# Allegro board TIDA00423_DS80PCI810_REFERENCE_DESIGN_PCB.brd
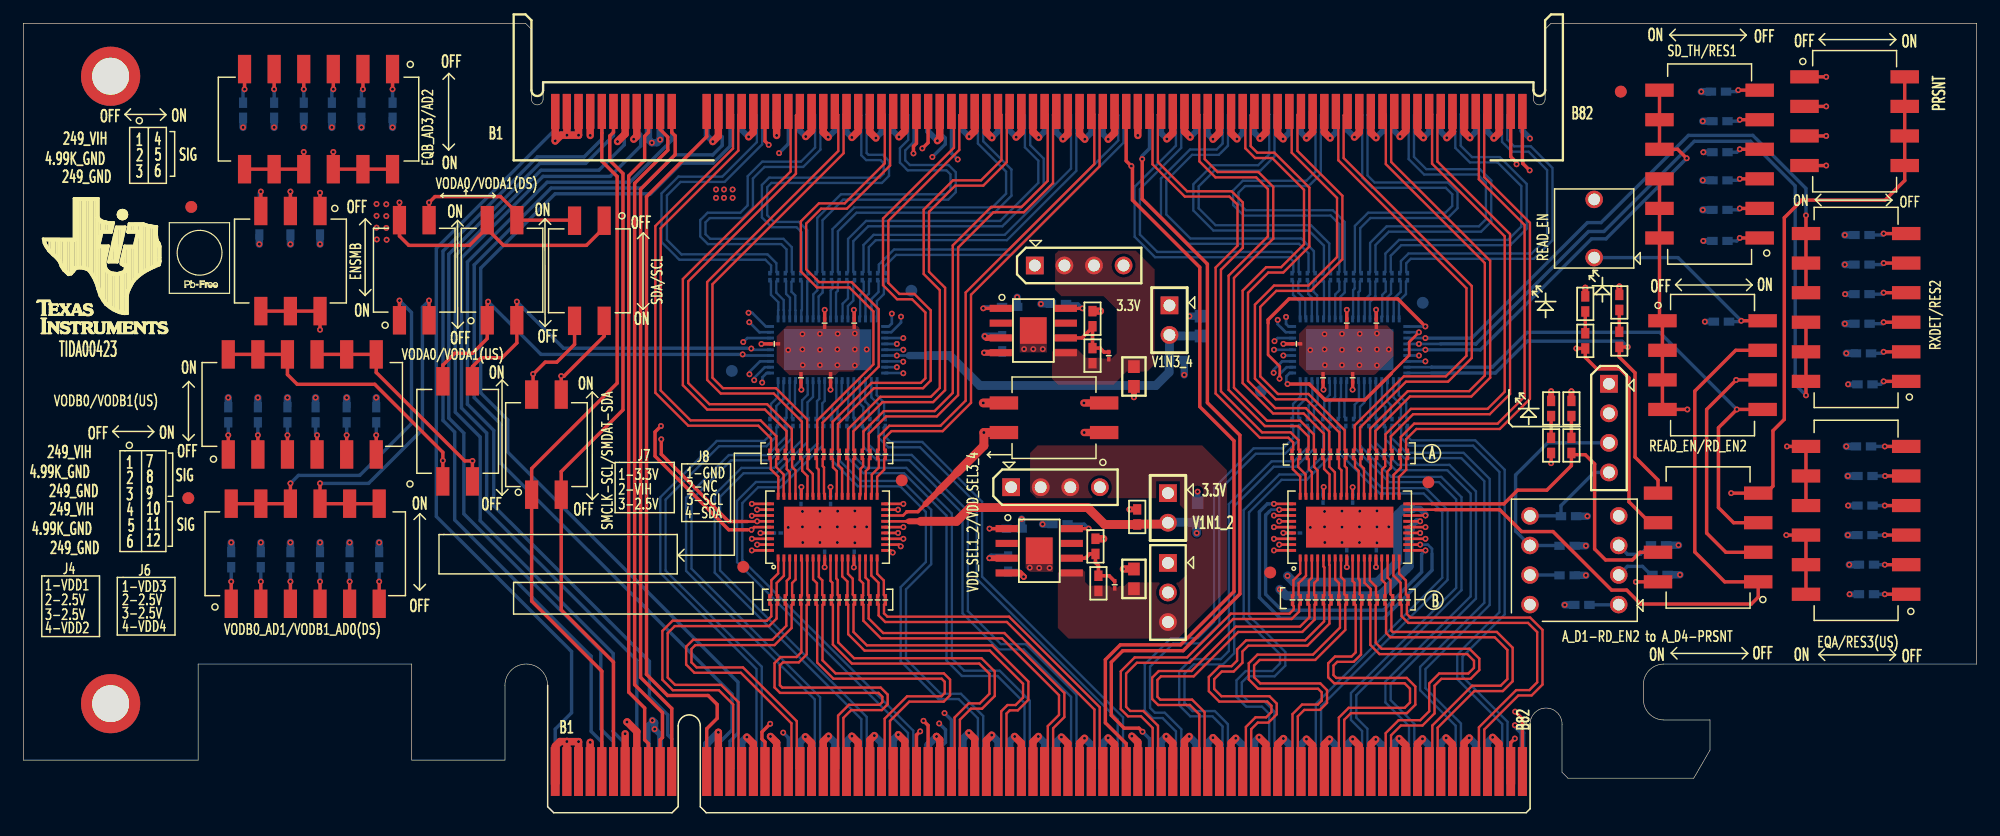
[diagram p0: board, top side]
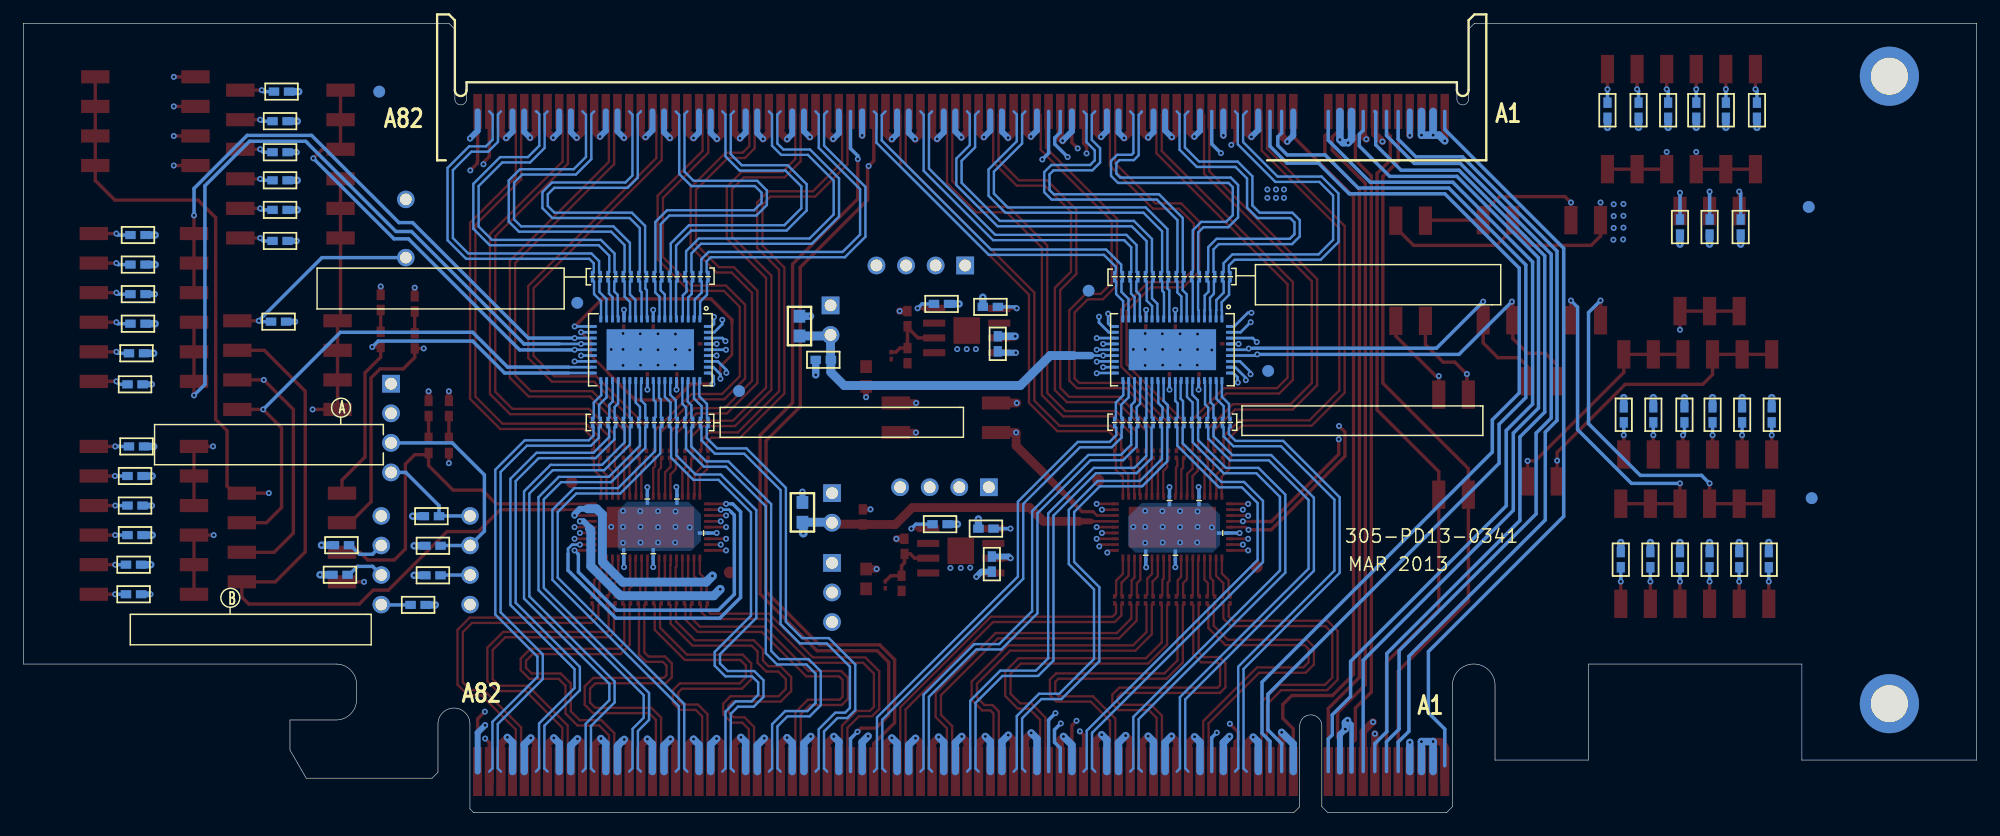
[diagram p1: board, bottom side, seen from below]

Outline 167.64 x 67.82 mm; copper layers: TOP, GND1, POWER1, POWER2, GND2, BOTTOM. Coordinates in mm from the lower left corner of the outline.
Outline path: 0,67.82 0,4.52 15,4.52 15,12.77 33.33,12.77 33.33,4.52 41.34,4.52 41.34,10.95 arc(43.16,12.77) 44.99,10.95 44.99,0.52 45.51,0 55.68,0 56.2,0.52 56.2,7.47 arc(57.15,8.42) 58.1,7.47 58.1,0.51 58.61,0 128.98,0 129.31,0.34 129.31,7.62 arc(130.68,8.99) 132.05,7.62 132.05,3.47 132.56,2.97 143.36,2.97 144.75,5.39 144.75,7.97 140.79,7.97 arc(139.55,8.48) 139.04,9.72 139.04,11.02 arc(139.55,12.26) 140.79,12.77 167.64,12.77 167.64,67.82 131.11,67.82 130.6,67.31 130.6,61.31 arc(130.1,60.81) 129.6,61.31 129.6,62.74 44.61,62.74 44.61,61.31 arc(44.11,60.81) 43.61,61.31 43.61,67.31 43.1,67.82 0,67.82

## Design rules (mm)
net group A_D1: nets A_D1 N144905650
net group A_D2: nets A_D2 N144912360
net group A_D3: nets A_D3 N144909880
net group A_D4: nets A_D4 N144914850
net group PERN0: nets N708449616 PERN0
net group PERN0_C: nets N144793501 PERN0_C
net group PERN1: nets N708449621 PERN1
net group PERN1_C: nets N144768421 PERN1_C
net group PERN2: nets N708449625 PERN2
net group PERN2_C: nets N144768181 PERN2_C
net group PERN3: nets N708449629 PERN3
net group PERN3_C: nets N144794701 PERN3_C
net group PERN4: nets N708449635 PERN4
net group PERN4_C: nets N144796981 PERN4_C
net group PERN5: nets N708449639 PERN5
net group PERN5_C: nets N144780601 PERN5_C
net group PERN6: nets N708449643 PERN6
net group PERN6_C: nets N144778981 PERN6_C
net group PERN7: nets N708449647 PERN7
net group PERN7_C: nets N144766261 PERN7_C
net group PERN8: nets N708449652 PERN8
net group PERN8_C: nets N144777781 PERN8_C
net group PERN9: nets N708449656 PERN9
net group PERN9_C: nets N144778201 PERN9_C
net group PERN10: nets N708449660 PERN10
net group PERN10_C: nets N144778741 PERN10_C
net group PERN11: nets N708449664 PERN11
net group PERN11_C: nets N144777421 PERN11_C
net group PERN12: nets N708449668 PERN12
net group PERN12_C: nets N144796741 PERN12_C
net group PERN13: nets N708449672 PERN13
net group PERN13_C: nets N144769921 PERN13_C
net group PERN14: nets N708449676 PERN14
net group PERN14_C: nets N144775501 PERN14_C
net group PERN15: nets N708449680 PERN15
net group PERN15_C: nets N144767221 PERN15_C
net group PERP0: nets N708449615 PERP0
net group PERP0_C: nets N144792241 PERP0_C
net group PERP1: nets N708449620 PERP1
net group PERP1_C: nets N144791101 PERP1_C
net group PERP2: nets N708449624 PERP2
net group PERP2_C: nets N144794401 PERP2_C
net group PERP3: nets N708449628 PERP3
net group PERP3_C: nets N144773581 PERP3_C
net group PERP4: nets N708449634 PERP4
net group PERP4_C: nets N144792841 PERP4_C
net group PERP5: nets N708449638 PERP5
net group PERP5_C: nets N144771181 PERP5_C
net group PERP6: nets N708449642 PERP6
net group PERP6_C: nets N144780361 PERP6_C
net group PERP7: nets N708449646 PERP7
net group PERP7_C: nets N144773341 PERP7_C
net group PERP8: nets N708449651 PERP8
net group PERP8_C: nets N144769021 PERP8_C
net group PERP9: nets N708449655 PERP9
net group PERP9_C: nets N144788821 PERP9_C
net group PERP10: nets N708449659 PERP10
net group PERP10_C: nets N144768781 PERP10_C
net group PERP11: nets N708449663 PERP11
net group PERP11_C: nets N144772741 PERP11_C
net group PERP12: nets N708449667 PERP12
net group PERP12_C: nets N144777181 PERP12_C
net group PERP13: nets N708449671 PERP13
net group PERP13_C: nets N144766561 PERP13_C
net group PERP14: nets N708449675 PERP14
net group PERP14_C: nets N144795421 PERP14_C
net group PERP15: nets N708449679 PERP15
net group PERP15_C: nets N144788221 PERP15_C
net group PETN0: nets N708449696 PETN0
net group PETN0_C: nets N144795060 PETN0_C
net group PETN1: nets N7084496101 PETN1
net group PETN1_C: nets N144774480 PETN1_C
net group PETN2: nets N7084496105 PETN2
net group PETN2_C: nets N144776640 PETN2_C
net group PETN3: nets N7084496109 PETN3
net group PETN3_C: nets N144771900 PETN3_C
net group PETN4: nets N7084496115 PETN4
net group PETN4_C: nets N144790620 PETN4_C
net group PETN5: nets N7084496119 PETN5
net group PETN5_C: nets N144770280 PETN5_C
net group PETN6: nets N7084496123 PETN6
net group PETN6_C: nets N144771420 PETN6_C
net group PETN7: nets N7084496127 PETN7
net group PETN7_C: nets N144775140 PETN7_C
net group PETN8: nets N7084496132 PETN8
net group PETN8_C: nets N144795720 PETN8_C
net group PETN9: nets N7084496136 PETN9
net group PETN9_C: nets N144776160 PETN9_C
net group PETN10: nets N7084496140 PETN10
net group PETN10_C: nets N144770880 PETN10_C
net group PETN11: nets N7084496144 PETN11
net group PETN11_C: nets N144790260 PETN11_C
net group PETN12: nets N7084496148 PETN12
net group PETN12_C: nets N144772500 PETN12_C
net group PETN13: nets N7084496152 PETN13
net group PETN13_C: nets N144778500 PETN13_C
net group PETN14: nets N7084496156 PETN14
net group PETN14_C: nets N144774000 PETN14_C
net group PETN15: nets N7084496160 PETN15
net group PETN15_C: nets N144791880 PETN15_C
net group PETP0: nets N708449695 PETP0
net group PETP0_C: nets N144769680 PETP0_C
net group PETP1: nets N7084496100 PETP1
net group PETP1_C: nets N144776880 PETP1_C
net group PETP2: nets N7084496104 PETP2
net group PETP2_C: nets N144766980 PETP2_C
net group PETP3: nets N7084496108 PETP3
net group PETP3_C: nets N144779460 PETP3_C
net group PETP4: nets N7084496114 PETP4
net group PETP4_C: nets N144779220 PETP4_C
net group PETP5: nets N7084496118 PETP5
net group PETP5_C: nets N144796260 PETP5_C
net group PETP6: nets N7084496122 PETP6
net group PETP6_C: nets N144789780 PETP6_C
net group PETP7: nets N7084496126 PETP7
net group PETP7_C: nets N144765660 PETP7_C
net group PETP8: nets N7084496131 PETP8
net group PETP8_C: nets N144789240 PETP8_C
net group PETP9: nets N7084496135 PETP9
net group PETP9_C: nets N144794040 PETP9_C
net group PETP10: nets N7084496139 PETP10
net group PETP10_C: nets N144770640 PETP10_C
net group PETP11: nets N7084496143 PETP11
net group PETP11_C: nets N144774240 PETP11_C
net group PETP12: nets N7084496147 PETP12
net group PETP12_C: nets N144793080 PETP12_C
net group PETP13: nets N7084496151 PETP13
net group PETP13_C: nets N144780060 PETP13_C
net group PETP14: nets N7084496155 PETP14
net group PETP14_C: nets N144767760 PETP14_C
net group PETP15: nets N7084496159 PETP15
net group PETP15_C: nets N144772140 PETP15_C
net group VOUT1_2: nets N14347575 VOUT1_2
net group VOUT3_4: nets N14379574 VOUT3_4
net group 3_3V: nets 3_3V N14347847 N14379914
net group SCL: nets N14519010 N14693554 N143603151 N143605671 N144870781 N144872810 N144872813 N144873671 N144875811 N144883340 N144883343 N144883781 N144885701 N144890181 N144891221 SCL SDA VIH

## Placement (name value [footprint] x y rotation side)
C1  0.1uF  [0201]  68.77 22.12 270 bottom
C2  0.1uF  [0201]  64.71 24.03 180 bottom
C3  0.1uF  [0201]  69.28 26.82 90 bottom
C4  0.1uF  [0201]  66.74 26.82 90 bottom
C5  0.1uF  [0201]  71.31 22.12 270 bottom
C6  0.1uF  [0201]  114.08 26.95 90 bottom
C7  0.1uF  [0201]  111.54 26.95 90 bottom
C8  0.1uF  [0201]  109.26 24.03 180 bottom
C9  0.1uF  [0201]  113.58 22.25 270 bottom
C10  0.1uF  [0201]  116.12 22.25 270 bottom
C11  0.1uF  [0201]  71.31 42.06 90 top
C12  0.1uF  [0201]  68.77 42.06 90 top
C13  0.1uF  [0201]  64.45 40.28 180 top
C14  0.1uF  [0201]  69.28 37.36 270 top
C15  0.1uF  [0201]  66.74 37.36 270 top
C16  0.1uF  [0201]  116.12 42.06 90 top
C17  0.1uF  [0201]  113.58 42.06 90 top
C18  0.1uF  [0201]  109.26 40.28 180 top
C19  0.1uF  [0201]  114.08 37.36 270 top
C20  0.1uF  [0201]  111.54 37.36 270 top
C21  10uF  [0603]  100.77 25.8 270 bottom
C22  10uF  [0603]  101.03 41.81 270 bottom
C23  4.7uF  [0402]  84.52 21.36 270 bottom
C24  4.7uF  [0402]  84.01 40.28 270 bottom
C25  0.01uF  [0402]  85.03 24.41 0 bottom
C26  0.01uF  [0402]  84.65 43.46 0 bottom
C27  10uF  [0603]  95.31 20.09 90 top
C28  10uF  [0603]  95.31 37.47 270 top
C29  1nF  [0201]  93.66 19.58 90 top
C30  1nF  [0201]  93.15 39.27 90 top
C31  0.22uF  [0201]  64.07 18.28 90 top
C32  0.22uF  [0201]  64.73 18.28 90 top
C33  0.22uF  [0201]  65.39 18.28 90 top
C34  0.22uF  [0201]  66.05 18.28 90 top
C35  0.22uF  [0201]  66.71 18.28 90 top
C36  0.22uF  [0201]  67.37 18.28 90 top
C37  0.22uF  [0201]  68.03 18.28 90 top
C38  0.22uF  [0201]  68.69 18.28 90 top
C39  0.22uF  [0201]  69.36 18.28 90 top
C40  0.22uF  [0201]  70.02 18.28 90 top
C41  0.22uF  [0201]  70.68 18.28 90 top
C42  0.22uF  [0201]  71.34 18.28 90 top
C43  0.22uF  [0201]  72 18.28 90 top
C44  0.22uF  [0201]  72.66 18.28 90 top
C45  0.22uF  [0201]  73.32 18.28 90 top
C46  0.22uF  [0201]  73.98 18.28 90 top
C47  0.22uF  [0201]  108.93 18.28 90 top
C48  0.22uF  [0201]  109.59 18.28 90 top
C49  0.22uF  [0201]  110.25 18.28 90 top
C50  0.22uF  [0201]  110.91 18.28 90 top
C51  0.22uF  [0201]  111.57 18.28 90 top
C52  0.22uF  [0201]  112.23 18.28 90 top
C53  0.22uF  [0201]  112.89 18.28 90 top
C54  0.22uF  [0201]  113.55 18.28 90 top
C55  0.22uF  [0201]  114.21 18.28 90 top
C56  0.22uF  [0201]  114.87 18.28 90 top
C57  0.22uF  [0201]  115.53 18.28 90 top
C58  0.22uF  [0201]  116.19 18.28 90 top
C59  0.22uF  [0201]  116.85 18.28 90 top
C60  0.22uF  [0201]  117.51 18.28 90 top
C61  0.22uF  [0201]  118.17 18.28 90 top
C62  0.22uF  [0201]  118.83 18.28 90 top
C63  0.22uF  [0201]  64.07 33.52 270 bottom
C64  0.22uF  [0201]  64.73 33.52 270 bottom
C65  0.22uF  [0201]  65.39 33.52 270 bottom
C66  0.22uF  [0201]  66.05 33.52 270 bottom
C67  0.22uF  [0201]  66.71 33.52 270 bottom
C68  0.22uF  [0201]  67.37 33.52 270 bottom
C69  0.22uF  [0201]  68.03 33.52 270 bottom
C70  0.22uF  [0201]  68.69 33.52 270 bottom
C71  0.22uF  [0201]  69.36 33.52 270 bottom
C72  0.22uF  [0201]  70.02 33.52 270 bottom
C73  0.22uF  [0201]  70.68 33.52 270 bottom
C74  0.22uF  [0201]  71.34 33.52 270 bottom
C75  0.22uF  [0201]  72 33.52 270 bottom
C76  0.22uF  [0201]  72.66 33.52 270 bottom
C77  0.22uF  [0201]  73.32 33.52 270 bottom
C78  0.22uF  [0201]  73.98 33.52 270 bottom
C79  0.22uF  [0201]  108.88 33.52 270 bottom
C80  0.22uF  [0201]  109.54 33.52 270 bottom
C81  0.22uF  [0201]  110.2 33.52 270 bottom
C82  0.22uF  [0201]  110.86 33.52 270 bottom
C83  0.22uF  [0201]  111.52 33.52 270 bottom
C84  0.22uF  [0201]  112.18 33.52 270 bottom
C85  0.22uF  [0201]  112.84 33.52 270 bottom
C86  0.22uF  [0201]  113.5 33.52 270 bottom
C87  0.22uF  [0201]  114.16 33.52 270 bottom
C88  0.22uF  [0201]  114.82 33.52 270 bottom
C89  0.22uF  [0201]  115.48 33.52 270 bottom
C90  0.22uF  [0201]  116.14 33.52 270 bottom
C91  0.22uF  [0201]  116.8 33.52 270 bottom
C92  0.22uF  [0201]  117.46 33.52 270 bottom
C93  0.22uF  [0201]  118.12 33.52 270 bottom
C94  0.22uF  [0201]  118.78 33.52 270 bottom
C95  0.22uF  [0201]  64.07 30.79 270 top
C96  0.22uF  [0201]  64.73 30.79 270 top
C97  0.22uF  [0201]  65.39 30.79 270 top
C98  0.22uF  [0201]  66.05 30.79 270 top
C99  0.22uF  [0201]  66.71 30.79 270 top
C100  0.22uF  [0201]  67.37 30.79 270 top
C101  0.22uF  [0201]  68.03 30.79 270 top
C102  0.22uF  [0201]  68.69 30.79 270 top
C103  0.22uF  [0201]  69.36 30.79 270 top
C104  0.22uF  [0201]  70.02 30.79 270 top
C105  0.22uF  [0201]  70.68 30.79 270 top
C106  0.22uF  [0201]  71.34 30.79 270 top
C107  0.22uF  [0201]  72 30.79 270 top
C108  0.22uF  [0201]  72.66 30.79 270 top
C109  0.22uF  [0201]  73.32 30.79 270 top
C110  0.22uF  [0201]  73.98 30.79 270 top
C111  0.22uF  [0201]  108.88 30.79 270 top
C112  0.22uF  [0201]  109.54 30.79 270 top
C113  0.22uF  [0201]  110.2 30.79 270 top
C114  0.22uF  [0201]  110.86 30.79 270 top
C115  0.22uF  [0201]  111.52 30.79 270 top
C116  0.22uF  [0201]  112.18 30.79 270 top
C117  0.22uF  [0201]  112.84 30.79 270 top
C118  0.22uF  [0201]  113.5 30.79 270 top
C119  0.22uF  [0201]  114.16 30.79 270 top
C120  0.22uF  [0201]  114.82 30.79 270 top
C121  0.22uF  [0201]  115.48 30.79 270 top
C122  0.22uF  [0201]  116.14 30.79 270 top
C123  0.22uF  [0201]  116.8 30.79 270 top
C124  0.22uF  [0201]  117.46 30.79 270 top
C125  0.22uF  [0201]  118.12 30.79 270 top
C126  0.22uF  [0201]  118.78 30.79 270 top
C127  0.22uF  [0201]  64.07 46.05 90 bottom
C128  0.22uF  [0201]  64.73 46.05 90 bottom
C129  0.22uF  [0201]  65.39 46.05 90 bottom
C130  0.22uF  [0201]  66.05 46.05 90 bottom
C131  0.22uF  [0201]  66.71 46.05 90 bottom
C132  0.22uF  [0201]  67.37 46.05 90 bottom
C133  0.22uF  [0201]  68.03 46.05 90 bottom
C134  0.22uF  [0201]  68.69 46.05 90 bottom
C135  0.22uF  [0201]  69.36 46.05 90 bottom
C136  0.22uF  [0201]  70.02 46.05 90 bottom
C137  0.22uF  [0201]  70.68 46.05 90 bottom
C138  0.22uF  [0201]  71.34 46.05 90 bottom
C139  0.22uF  [0201]  72 46.05 90 bottom
C140  0.22uF  [0201]  72.66 46.05 90 bottom
C141  0.22uF  [0201]  73.32 46.05 90 bottom
C142  0.22uF  [0201]  73.98 46.05 90 bottom
C143  0.22uF  [0201]  108.88 46.05 90 bottom
C144  0.22uF  [0201]  109.54 46.05 90 bottom
C145  0.22uF  [0201]  110.2 46.05 90 bottom
C146  0.22uF  [0201]  110.86 46.05 90 bottom
C147  0.22uF  [0201]  111.52 46.05 90 bottom
C148  0.22uF  [0201]  112.18 46.05 90 bottom
C149  0.22uF  [0201]  112.84 46.05 90 bottom
C150  0.22uF  [0201]  113.5 46.05 90 bottom
C151  0.22uF  [0201]  114.16 46.05 90 bottom
C152  0.22uF  [0201]  114.82 46.05 90 bottom
C153  0.22uF  [0201]  115.48 46.05 90 bottom
C154  0.22uF  [0201]  116.14 46.05 90 bottom
C155  0.22uF  [0201]  116.8 46.05 90 bottom
C156  0.22uF  [0201]  117.46 46.05 90 bottom
C157  0.22uF  [0201]  118.12 46.05 90 bottom
C158  0.22uF  [0201]  118.78 46.05 90 bottom
C160  1uF  [0402]  95.59 25.41 270 top
C161  1uF  [0402]  98.98 38.91 180 bottom
D1  SML-P12PTT86  [0402]  131.12 34.73 270 top
D2  SML-P12PTT86  [0402]  132.86 34.73 270 top
D3  SML-P12PTT86  [0402]  134.05 43.71 270 top
D4  SML-P12PTT86  [0402]  136.97 43.84 270 top
J1  -  [PCIE_16X_EDGE_FINGER]  53.65 3.54 0 top
J2  -  [NWE82DHRN-T9410]  86.94 68.58 0 top
J3  2 HEADER  [2_HEADER]  98.23 27.45 270 top
J4  4 HEADER  [4_HEADER]  84.77 27.96 0 top
J5  2 HEADER  [2_HEADER]  98.36 43.58 270 top
J6  4 HEADER  [4_HEADER]  86.8 47.01 0 top
J7  3 HEADER  [3_HEADER]  98.23 21.46 270 top
J8  4 HEADER  [4_HEADER]  136.08 36.85 270 top
J9  4808-3004-CP  [DIP8]  133.11 21.69 90 top
NOREF  -  [unnamed]  7.49 63.27 0 top
NOREF#2  -  [#2]  0 4.52 90 top
NOREF#3  -  [unnamed]  14.16 27.02 0 top
NOREF#4  -  [unnamed]  75.39 28.55 0 top
NOREF#5  -  [unnamed]  137.1 61.95 0 top
NOREF#6  -  [#2]  33.33 4.52 0 top
NOREF#7  -  [unnamed]  107.01 20.64 0 top
NOREF#8  -  [#2]  0 68.58 0 top
NOREF#9  -  [#2]  0 4.52 0 top
NOREF#10  -  [unnamed]  61.79 21.12 0 top
NOREF#11  -  [unnamed]  7.49 9.37 0 top
NOREF#12  -  [unnamed]  14.41 52.04 0 top
NOREF#13  -  [#2]  166.88 13.53 90 top
NOREF#14  -  [#2]  15 12.77 0 top
NOREF#15  -  [unnamed]  120.58 28.38 0 top
NOREF#16  -  [unnamed]  137.1 61.95 180 bottom
NOREF#17  -  [unnamed]  60.81 37.95 180 bottom
NOREF#18  -  [unnamed]  120.1 43.81 180 bottom
NOREF#19  -  [unnamed]  76.21 44.84 180 bottom
NOREF#20  -  [unnamed]  106.22 36.23 180 bottom
NOREF#21  -  [unnamed]  14.41 52.04 180 bottom
NOREF#22  -  [unnamed]  14.16 27.02 180 bottom
R1  1.5k  [0402]  92.27 19.71 270 top
R2  1k  [0402]  92.01 22.88 270 top
R3  51k  [0402]  88.96 24.79 0 bottom
R4  1.5k  [0402]  91.76 39.27 270 top
R5  1k  [0402]  91.76 42.44 270 top
R6  51k  [0402]  88.84 43.71 0 bottom
R7  220  [0402]  131.12 31.55 270 top
R8  220  [0402]  132.86 31.55 270 top
R9  220  [0402]  134.05 40.54 270 top
R10  220  [0402]  136.97 40.66 270 top
R11  249  [0402]  31.69 60.35 90 bottom
R12  4.99k  [0402]  29.02 60.35 90 bottom
R13  249  [0402]  26.48 60.35 90 bottom
R14  249  [0402]  24.07 60.35 90 bottom
R15  4.99k  [0402]  21.53 60.35 90 bottom
R16  249  [0402]  18.86 60.35 90 bottom
R17  249  [0402]  25.46 50.31 90 bottom
R18  4.99k  [0402]  22.92 50.31 90 bottom
R19  249  [0402]  20.26 50.31 90 bottom
R20  249  [0402]  17.59 34.19 270 bottom
R21  4.99k  [0402]  20.13 34.19 270 bottom
R22  249  [0402]  22.67 34.19 270 bottom
R23  249  [0402]  25.08 34.19 270 bottom
R24  4.99k  [0402]  27.75 34.19 270 bottom
R25  249  [0402]  30.29 34.19 270 bottom
R26  249  [0402]  17.84 21.74 270 bottom
R27  4.99k  [0402]  20.38 21.74 270 bottom
R28  249  [0402]  22.92 21.74 270 bottom
R29  249  [0402]  25.46 21.74 270 bottom
R30  4.99k  [0402]  28 21.74 270 bottom
R31  249  [0402]  30.54 21.74 270 bottom
R32  249  [0402]  145.61 49.12 0 bottom
R33  4.99k  [0402]  145.61 51.79 0 bottom
R34  249  [0402]  145.61 54.33 0 bottom
R35  249  [0402]  145.61 56.74 0 bottom
R36  4.99k  [0402]  145.61 59.41 0 bottom
R37  249  [0402]  145.48 61.95 0 bottom
R38  249  [0402]  158.05 36.8 0 bottom
R39  4.99k  [0402]  157.92 39.47 0 bottom
R40  249  [0402]  157.8 42.01 0 bottom
R41  249  [0402]  157.8 44.55 0 bottom
R42  4.99k  [0402]  157.8 47.09 0 bottom
R43  249  [0402]  157.8 49.63 0 bottom
R44  249  [0402]  158.18 18.77 0 bottom
R45  4.99k  [0402]  158.18 21.31 0 bottom
R46  249  [0402]  158.05 23.85 0 bottom
R47  249  [0402]  158.05 26.39 0 bottom
R48  4.99k  [0402]  158.05 28.93 0 bottom
R49  249  [0402]  157.92 31.47 0 bottom
R50  1k  [0402]  133.76 17.85 0 bottom
R51  1k  [0402]  140.46 20.44 180 bottom
R52  1k  [0402]  140.34 22.98 180 bottom
R53  1k  [0402]  145.73 42.19 0 bottom
R54  1k  [0402]  132.49 20.39 0 bottom
R55  2k  [0402]  132.49 22.93 0 bottom
R56  2k  [0402]  132.61 25.47 0 bottom
SW1  -  [219-6MST]  25.34 59.59 180 top
SW2  -  [219-3MST]  22.92 47.39 180 top
SW3  -  [219-6MST]  23.94 35.07 0 top
SW4  -  [219-2MST]  48.58 46.56 180 top
SW5  -  [219-6MST]  24.19 22.25 0 top
SW6  -  [219-6MST]  144.72 55.72 90 top
SW7  -  [219-2MST]  88.46 33.93 90 top
SW8  -  [219-4MST]  144.97 39.72 270 top
SW9  -  [219-4MST]  144.59 22.37 90 top
SW10  -  [219-6MST]  157.29 43.41 90 top
SW11  -  [219-6MST]  157.29 25.12 90 top
SW12  -  [219-2MST]  44.89 31.62 0 top
SW13  -  [EVQ-21505R]  134.81 50.19 90 top
SW14  -  [219-4MST]  157.16 60.68 270 top
SW15  -  [219-2MST]  41.08 46.61 0 top
SW16  -  [219-2MST]  37.27 32.76 0 top
SW17  -  [219-2MST]  33.55 46.61 0 top
U1  DS80PCI800  [54_LLP]  69.02 24.53 0 top
U2  DS80PCI800  [54_LLP]  113.83 24.53 0 top
U3  DS80PCI800  [54_LLP]  69.02 39.77 0 bottom
U4  DS80PCI800  [54_LLP]  113.83 39.77 0 bottom
U5  LP3878-ADJ  [PSOP-8]  87.19 22.5 0 top
U6  LP3878-ADJ  [PSOP-8]  86.68 41.42 0 top

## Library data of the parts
C1-C20 = C_0: signal model: DEFAULT_CAPACITOR_100000pF_2_1
C21 C22 C27 C28 = C_0: signal model: DEFAULT_CAPACITOR_1e+07pF_2_1
C23 C24 = C_0: signal model: DEFAULT_CAPACITOR_4.7e+06pF_2_1
C25 C26 = C_0: signal model: DEFAULT_CAPACITOR_10000pF_2_1
C29 C30 = C_0: signal model: DEFAULT_CAPACITOR_1000pF_2_1
C31-C158 = C_0: signal model: DEFAULT_CAPACITOR_220000pF_2_1
C160 C161 = C: signal model: DEFAULT_CAPACITOR_1e+06pF_2_1
D1-D4 = 1091QM_0
J1 = PCIE_16X_EDGE_FINGER
J2 = NWE82DHRN-T9410
J3 J5 = HEADER 2
J4 J6 J8 = 4 HEADER
J7 = HEADER 3
J9 = DIP8 SOCKET
R1 R4 = RESISTOR/SM: signal model: DEFAULT_RESISTOR_1500OHM_2_1
R2 R5 R53 R54 = RESISTOR/SM: signal model: DEFAULT_RESISTOR_1000OHM_2_1
R3 R6 = RESISTOR/SM: signal model: DEFAULT_RESISTOR_51000OHM_2_1
R7 R8 = R_0: signal model: DEFAULT_RESISTOR_0.001OHM_2_1
R9 R10 = R_0: signal model: DEFAULT_RESISTOR_220OHM_2_1
R11-R13 R16 R37 R38 R42 = RESISTOR: signal model: DEFAULT_RESISTOR_0.001OHM_2_1
R14 R15 R17-R36 R39-R41 R43-R49 = RESISTOR: signal model: DEFAULT_RESISTOR_33OHM_2_1
R50-R52 = RESISTOR: signal model: DEFAULT_RESISTOR_1000OHM_2_1
R55 R56 = RESISTOR/SM: signal model: DEFAULT_RESISTOR_2000OHM_2_1
SW1 SW3 SW5 SW6 SW10 SW11 = SW DIP-6/SM
SW2 = SW DIP-3/SM
SW4 SW7 SW12 SW15-SW17 = SW DIP-2/SM
SW8 SW9 SW14 = SW DIP-4/SM
SW13 = SW PUSHBUTTON-SPST
U1-U4 = DS80PCI800
U5 U6 = LP3878-ADJ_0

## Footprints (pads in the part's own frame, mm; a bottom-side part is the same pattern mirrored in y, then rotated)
2_HEADER
  rect 1.524x1.524 hole 1.016: 1(0,0)
  round 1.524 hole 1.016: 2(2.54,0)
3_HEADER
  rect 1.524x1.524 hole 1.016: 1(0,0)
  round 1.524 hole 1.016: 2(2.54,0) 3(5.08,0)
4_HEADER
  rect 1.524x1.524 hole 1.016: 1(0,0)
  round 1.524 hole 1.016: 2(2.54,0) 3(5.08,0) 4(7.62,0)
54_LLP
  rect 0.25x0.6 smd: 1(-4.25,-2.65) 2(-3.75,-2.65) 3(-3.25,-2.65) 4(-2.75,-2.65) 5(-2.25,-2.65) 6(-1.75,-2.65) 7(-1.25,-2.65) 8(-0.75,-2.65) 9(-0.25,-2.65) 10(0.25,-2.65) 11(0.75,-2.65) 12(1.25,-2.65) 13(1.75,-2.65) 14(2.25,-2.65) 15(2.75,-2.65) 16(3.25,-2.65) 17(3.75,-2.65) 18(4.25,-2.65) 28(4.25,2.65) 29(3.75,2.65) 30(3.25,2.65) 31(2.75,2.65) 32(2.25,2.65) 33(1.75,2.65) 34(1.25,2.65) 35(0.75,2.65) 36(0.25,2.65) 37(-0.25,2.65) 38(-0.75,2.65) 39(-1.25,2.65) 40(-1.75,2.65) 41(-2.25,2.65) 42(-2.75,2.65) 43(-3.25,2.65) 44(-3.75,2.65) 45(-4.25,2.65)
  rect 0.6x0.25 smd: 19(4.9,-2) 20(4.9,-1.5) 21(4.9,-1) 22(4.9,-0.5) 23(4.9,0) 24(4.9,0.5) 25(4.9,1) 26(4.9,1.5) 27(4.9,2) 46(-4.9,2) 47(-4.9,1.5) 48(-4.9,1) 49(-4.9,0.5) 50(-4.9,0) 51(-4.9,-0.5) 52(-4.9,-1) 53(-4.9,-1.5) 54(-4.9,-2)
  rect 7.5x3.51 smd: 55(0,0)
0201
  rect 0.4x0.297 smd: 1(-0.3,0) 2(0.3,0)
219-2MST
  rect 1.13x2.44 smd: 1(-1.27,-4.3) 2(1.27,-4.3) 3(1.27,4.3) 4(-1.27,4.3)
219-3MST
  rect 1.13x2.44 smd: 1(-2.54,-4.3) 2(0,-4.3) 3(2.54,-4.3) 4(2.54,4.3) 5(0,4.3) 6(-2.54,4.3)
219-4MST
  rect 1.13x2.44 smd: 1(-2.54,-4.3) 2(0,-4.3) 3(2.54,-4.3) 4(5.08,-4.3) 5(5.08,4.3) 6(2.54,4.3) 7(0,4.3) 8(-2.54,4.3)
219-6MST
  rect 1.13x2.44 smd: 1(-6.35,-4.3) 2(-3.81,-4.3) 3(-1.27,-4.3) 4(1.27,-4.3) 5(3.81,-4.3) 6(6.35,-4.3) 7(6.35,4.3) 8(3.81,4.3) 9(1.27,4.3) 10(-1.27,4.3) 11(-3.81,4.3) 12(-6.35,4.3)
0402
  rect 0.9x0.7 smd: 1(-0.65,0) 2(0.65,0)
0603
  rect 1.1x1 smd: 1(-0.85,0) 2(0.85,0)
DIP8
  round 1.5 hole 1: 1(-3.81,-3.81) 2(-1.27,-3.81) 3(1.27,-3.81) 4(3.81,-3.81) 5(3.81,3.81) 6(1.27,3.81) 7(-1.27,3.81) 8(-3.81,3.81)
EVQ-21505R
  round 1.5 hole 1: 1(-2.5,0) 2(2.5,0)
NWE82DHRN-T9410
  rect 0.7x3 smd: A1(-41.29,-8.332) A2(-40.29,-8.332) A3(-39.29,-8.332) A4(-38.29,-8.332) A5(-37.29,-8.332) A6(-36.29,-8.332) A7(-35.29,-8.332) A8(-34.29,-8.332) A9(-33.29,-8.332) A10(-32.29,-8.332) A11(-31.29,-8.332) A12(-28.29,-8.332) A13(-27.29,-8.332) A14(-26.29,-8.332) A15(-25.29,-8.332) A16(-24.29,-8.332) A17(-23.29,-8.332) A18(-22.29,-8.332) A19(-21.29,-8.332) A20(-20.29,-8.332) A21(-19.29,-8.332) A22(-18.29,-8.332) A23(-17.29,-8.332) A24(-16.29,-8.332) A25(-15.29,-8.332) A26(-14.29,-8.332) A27(-13.29,-8.332) A28(-12.29,-8.332) A29(-11.29,-8.332) A30(-10.29,-8.332) A31(-9.29,-8.332) A32(-8.29,-8.332) A33(-7.29,-8.332) A34(-6.29,-8.332) A35(-5.29,-8.332) A36(-4.29,-8.332) A37(-3.29,-8.332) A38(-2.29,-8.332) A39(-1.29,-8.332) A40(-0.29,-8.332) A41(0.71,-8.332) A42(1.71,-8.332) A43(2.71,-8.332) A44(3.71,-8.332) A45(4.71,-8.332) A46(5.71,-8.332) A47(6.71,-8.332) A48(7.71,-8.332) A49(8.71,-8.332) A50(9.71,-8.332) A51(10.71,-8.332) A52(11.71,-8.332) A53(12.71,-8.332) A54(13.71,-8.332) A55(14.71,-8.332) A56(15.71,-8.332) A57(16.71,-8.332) A58(17.71,-8.332) A59(18.71,-8.332) A60(19.71,-8.332) A61(20.71,-8.332) A62(21.71,-8.332) A63(22.71,-8.332) A64(23.71,-8.332) A65(24.71,-8.332) A66(25.71,-8.332) A67(26.71,-8.332) A68(27.71,-8.332) A69(28.71,-8.332) A70(29.71,-8.332) A71(30.71,-8.332) A72(31.71,-8.332) A73(32.71,-8.332) A74(33.71,-8.332) A75(34.71,-8.332) A76(35.71,-8.332) A77(36.71,-8.332) A78(37.71,-8.332) A79(38.71,-8.332) A80(39.71,-8.332) A81(40.71,-8.332) A82(41.71,-8.332) B1(-41.29,-8.332) B2(-40.29,-8.332) B3(-39.29,-8.332) B4(-38.29,-8.332) B5(-37.29,-8.332) B6(-36.29,-8.332) B7(-35.29,-8.332) B8(-34.29,-8.332) B9(-33.29,-8.332) B10(-32.29,-8.332) B11(-31.29,-8.332) B12(-28.29,-8.332) B13(-27.29,-8.332) B14(-26.29,-8.332) B15(-25.29,-8.332) B16(-24.29,-8.332) B17(-23.29,-8.332) B18(-22.29,-8.332) B19(-21.29,-8.332) B20(-20.29,-8.332) B21(-19.29,-8.332) B22(-18.29,-8.332) B23(-17.29,-8.332) B24(-16.29,-8.332) B25(-15.29,-8.332) B26(-14.29,-8.332) B27(-13.29,-8.332) B28(-12.29,-8.332) B29(-11.29,-8.332) B30(-10.29,-8.332) B31(-9.29,-8.332) B32(-8.29,-8.332) B33(-7.29,-8.332) B34(-6.29,-8.332) B35(-5.29,-8.332) B36(-4.29,-8.332) B37(-3.29,-8.332) B38(-2.29,-8.332) B39(-1.29,-8.332) B40(-0.29,-8.332) B41(0.71,-8.332) B42(1.71,-8.332) B43(2.71,-8.332) B44(3.71,-8.332) B45(4.71,-8.332) B46(5.71,-8.332) B47(6.71,-8.332) B48(7.71,-8.332) B49(8.71,-8.332) B50(9.71,-8.332) B51(10.71,-8.332) B52(11.71,-8.332) B53(12.71,-8.332) B54(13.71,-8.332) B55(14.71,-8.332) B56(15.71,-8.332) B57(16.71,-8.332) B58(17.71,-8.332) B59(18.71,-8.332) B60(19.71,-8.332) B61(20.71,-8.332) B62(21.71,-8.332) B63(22.71,-8.332) B64(23.71,-8.332) B65(24.71,-8.332) B66(25.71,-8.332) B67(26.71,-8.332) B68(27.71,-8.332) B69(28.71,-8.332) B70(29.71,-8.332) B71(30.71,-8.332) B72(31.71,-8.332) B73(32.71,-8.332) B74(33.71,-8.332) B75(34.71,-8.332) B76(35.71,-8.332) B77(36.71,-8.332) B78(37.71,-8.332) B79(38.71,-8.332) B80(39.71,-8.332) B81(40.71,-8.332) B82(41.71,-8.332)
PCIE_16X_EDGE_FINGER
  rect 0.76x3.2 smd: A1(-8,0.5) B81(74,0.5)
  rect 0.76x4.19 smd: A2(-7,0) A3(-6,0) A4(-5,0) A5(-4,0) A6(-3,0) A7(-2,0) A8(-1,0) A9(0,0) A10(1,0) A11(2,0) A12(5,0) A13(6,0) A14(7,0) A15(8,0) A16(9,0) A17(10,0) A18(11,0) A19(12,0) A20(13,0) A21(14,0) A22(15,0) A23(16,0) A24(17,0) A25(18,0) A26(19,0) A27(20,0) A28(21,0) A29(22,0) A30(23,0) A31(24,0) A32(25,0) A33(26,0) A34(27,0) A35(28,0) A36(29,0) A37(30,0) A38(31,0) A39(32,0) A40(33,0) A41(34,0) A42(35,0) A43(36,0) A44(37,0) A45(38,0) A46(39,0) A47(40,0) A48(41,0) A49(42,0) A50(43,0) A51(44,0) A52(45,0) A53(46,0) A54(47,0) A55(48,0) A56(49,0) A57(50,0) A58(51,0) A59(52,0) A60(53,0) A61(54,0) A62(55,0) A63(56,0) A64(57,0) A65(58,0) A66(59,0) A67(60,0) A68(61,0) A69(62,0) A70(63,0) A71(64,0) A72(65,0) A73(66,0) A74(67,0) A75(68,0) A76(69,0) A77(70,0) A78(71,0) A79(72,0) A80(73,0) A81(74,0) A82(75,0) B1(-8,0) B2(-7,0) B3(-6,0) B4(-5,0) B5(-4,0) B6(-3,0) B7(-2,0) B8(-1,0) B9(0,0) B10(1,0) B11(2,0) B12(5,0) B13(6,0) B14(7,0) B15(8,0) B16(9,0) B17(10,0) B18(11,0) B19(12,0) B20(13,0) B21(14,0) B22(15,0) B23(16,0) B24(17,0) B25(18,0) B26(19,0) B27(20,0) B28(21,0) B29(22,0) B30(23,0) B31(24,0) B32(25,0) B33(26,0) B34(27,0) B35(28,0) B36(29,0) B37(30,0) B38(31,0) B39(32,0) B40(33,0) B41(34,0) B42(35,0) B43(36,0) B44(37,0) B45(38,0) B46(39,0) B47(40,0) B48(41,0) B49(42,0) B50(43,0) B51(44,0) B52(45,0) B53(46,0) B54(47,0) B55(48,0) B56(49,0) B57(50,0) B58(51,0) B59(52,0) B60(53,0) B61(54,0) B62(55,0) B63(56,0) B64(57,0) B65(58,0) B66(59,0) B67(60,0) B68(61,0) B69(62,0) B70(63,0) B71(64,0) B72(65,0) B73(66,0) B74(67,0) B75(68,0) B76(69,0) B77(70,0) B78(71,0) B79(72,0) B80(73,0) B82(75,0)
PSOP-8
  rect 1.905x0.61 smd: 1(-2.794,1.905) 2(-2.794,0.635) 3(-2.794,-0.635) 4(-2.794,-1.905) 5(2.794,-1.905) 6(2.794,-0.635) 7(2.794,0.635) 8(2.794,1.905)
  rect 2.286x2.286 smd: 9(0,0)
unnamed
  round 5.08 hole 3.175: (0,0)

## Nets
12V: J1.A2 J1.A3 J1.B1 J1.B2 J1.B3 J2.A2 J2.A3 J2.B1 J2.B2 J2.B3
GND: C1.1 C2.1 C3.1 C4.1 C5.1 C6.1 C7.1 C8.1 C9.1 C10.1 C11.1 C12.1 C13.1 C14.1 C15.1 C16.1 C17.1 C18.1 C19.1 C20.1 C21.1 C22.1 C23.1 C24.1 C25.2 C26.2 C27.2 C28.2 C160.1 C161.1 D1.1(CATHODE) D2.1(CATHODE) D3.1(CATHODE) D4.1(CATHODE) J1.A4 J1.A12 J1.A15 J1.A18 J1.A20 J1.A23 J1.A24 J1.A27 J1.A28 J1.A31 J1.A34 J1.A37 J1.A38 J1.A41 J1.A42 J1.A45 J1.A46 J1.A49 J1.A51 J1.A54 J1.A55 J1.A58 J1.A59 J1.A62 J1.A63 J1.A66 J1.A67 J1.A70 J1.A71 J1.A74 J1.A75 J1.A78 J1.A79 J1.A82 J1.B4 J1.B7 J1.B13 J1.B16 J1.B18 J1.B21 J1.B22 J1.B25 J1.B26 J1.B29 J1.B32 J1.B35 J1.B36 J1.B39 J1.B40 J1.B43 J1.B44 J1.B47 J1.B49 J1.B52 J1.B53 J1.B56 J1.B57 J1.B60 J1.B61 J1.B64 J1.B65 J1.B68 J1.B69 J1.B72 J1.B73 J1.B76 J1.B77 J1.B80 J2.A4 J2.A12 J2.A15 J2.A18 J2.A20 J2.A23 J2.A24 J2.A27 J2.A28 J2.A31 J2.A34 J2.A37 J2.A38 J2.A41 J2.A42 J2.A45 J2.A46 J2.A49 J2.A51 J2.A54 J2.A55 J2.A58 J2.A59 J2.A62 J2.A63 J2.A66 J2.A67 J2.A70 J2.A71 J2.A74 J2.A75 J2.A78 J2.A79 J2.A82 J2.B4 J2.B7 J2.B13 J2.B16 J2.B18 J2.B21 J2.B22 J2.B25 J2.B26 J2.B29 J2.B32 J2.B35 J2.B36 J2.B39 J2.B40 J2.B43 J2.B44 J2.B47 J2.B49 J2.B52 J2.B53 J2.B56 J2.B57 J2.B60 J2.B61 J2.B64 J2.B65 J2.B68 J2.B69 J2.B72 J2.B73 J2.B76 J2.B77 J2.B80 J8.1 J9.4 R2.1 R5.1 R12.1 R13.1 R15.1 R16.1 R18.1 R19.1 R21.1 R22.1 R24.1 R25.1 R27.1 R28.1 R30.1 R31.1 R33.1 R34.1 R36.1 R37.1 R39.1 R40.1 R42.1 R43.1 R45.1 R46.1 R48.1 R49.1 R50.1 R51.1 R52.1 SW7.1(A1) SW7.2(A2) SW13.2 U1.55(DAP) U2.55(DAP) U3.55(DAP) U4.55(DAP) U5.3(GND) U5.9(DAP) U6.3(GND) U6.9(DAP)
VDD1: C1.2 C2.2 C3.2 C4.2 C5.2 J4.1 U1.9(VDD#9) U1.14(VDD#14) U1.36(VDD#36) U1.41(VDD#41) U1.51(VDD#51)
VDD2: C6.2 C7.2 C8.2 C9.2 C10.2 J4.4 U2.9(VDD#9) U2.14(VDD#14) U2.36(VDD#36) U2.41(VDD#41) U2.51(VDD#51)
VDD3: C11.2 C12.2 C13.2 C14.2 C15.2 J6.1 U3.9(VDD#9) U3.14(VDD#14) U3.36(VDD#36) U3.41(VDD#41) U3.51(VDD#51)
VDD4: C16.2 C17.2 C18.2 C19.2 C20.2 J6.4 U4.9(VDD#9) U4.14(VDD#14) U4.36(VDD#36) U4.41(VDD#41) U4.51(VDD#51)
VDD_SEL1_2: SW7.4(B1) U1.25(VDD_SEL) U2.25(VDD_SEL)
VDD_SEL3_4: SW7.3(B2) U3.25(VDD_SEL) U4.25(VDD_SEL)
VIN1_2: C21.2 C160.2 J3.2 U1.24(VIN) U2.24(VIN)
VIN3_4: C22.2 C161.2 J5.2 U3.24(VIN) U4.24(VIN)
3_3V: C23.2 C24.2 J1.A9 J1.A10 J1.B8 J2.A9 J2.A10 J2.B8 J3.1 J5.1 J7.1 R3.1 R6.1 U5.4(INPUT) U6.4(INPUT)
3_3VAUX: J1.B10 J2.B10
A_D1: R7.2 SW9.8(B1) U1.27(ALL_DONE)
A_D2: R8.2 SW9.7(B2) U2.27(ALL_DONE)
A_D3: R9.2 SW9.6(B3) U3.27(ALL_DONE)
A_D4: R10.2 SW9.5(B4) U4.27(ALL_DONE)
DEMA0_SDA_DS: SW4.1(A1) SW15.4(B1) SW17.4(B1) U1.49(DEMA0/SDA) U2.49(DEMA0/SDA)
DEMA0_SDA_US: SW15.1(A1) SW16.4(B1) U3.49(DEMA0/SDA) U4.49(DEMA0/SDA)
DEMA1_SCL_DS: SW4.2(A2) SW15.3(B2) SW17.3(B2) U1.50(DEMA1/SCL) U2.50(DEMA1/SCL)
DEMA1_SCL_US: SW15.2(A2) SW16.3(B2) U3.50(DEMA1/SCL) U4.50(DEMA1/SCL)
DEMB0_AD1_DS: SW5.10(B3) SW5.11(B2) SW5.12(B1) SW17.1(A1) U1.53(DEMB0/AD1) U2.53(DEMB0/AD1)
DEMB0_AD1_US: SW3.10(B3) SW3.11(B2) SW3.12(B1) SW16.1(A1) U3.53(DEMB0/AD1) U4.53(DEMB0/AD1)
DEMB1_AD0_DS: SW5.7(B6) SW5.8(B5) SW5.9(B4) SW17.2(A2) U1.54(DEMB1/AD0) U2.54(DEMB1/AD0)
DEMB1_AD0_US: SW3.7(B6) SW3.8(B5) SW3.9(B4) SW16.2(A2) U3.54(DEMB1/AD0) U4.54(DEMB1/AD0)
ENSMB: SW2.4(B3) SW2.5(B2) SW2.6(B1) U1.48(ENSMB) U2.48(ENSMB) U3.48(ENSMB) U4.48(ENSMB)
EQA0_DS: SW1.10(B3) SW1.11(B2) SW1.12(B1) U1.20(EQA0) U1.46(EQB0/AD3) U2.20(EQA0) U2.46(EQB0/AD3)
EQA0_US: SW11.10(B3) SW11.11(B2) SW11.12(B1) U3.20(EQA0) U3.46(EQB0/AD3) U4.20(EQA0) U4.46(EQB0/AD3)
EQA1_DS: SW1.7(B6) SW1.8(B5) SW1.9(B4) U1.19(EQA1) U1.47(EQB1/AD2) U2.19(EQA1) U2.47(EQB1/AD2)
EQA1_US: SW11.7(B6) SW11.8(B5) SW11.9(B4) U3.19(EQA1) U3.47(EQB1/AD2) U4.19(EQA1) U4.47(EQB1/AD2)
JTAG1: J1.B9 J2.B9
JTAG2: J1.A5 J2.A5
JTAG3: J1.A6 J2.A6
JTAG4: J1.A7 J2.A7
JTAG5: J1.A8 J2.A8
PERN0: C64.1 U3.44(OB_0-)
PERN0_C: C128.1 U3.2(IB_0-)
PERN1: C66.1 U3.42(OB_1-)
PERN1_C: C130.1 U3.4(IB_1-)
PERN2: C68.1 U3.39(OB_2-)
PERN2_C: C132.1 U3.6(IB_2-)
PERN3: C70.1 U3.37(OB_3-)
PERN3_C: C134.1 U3.8(IB_3-)
PERN4: C72.1 U3.34(OA_0-)
PERN4_C: C136.1 U3.11(IA_0-)
PERN5: C74.1 U3.32(OA_1-)
PERN5_C: C138.1 U3.13(IA_1-)
PERN6: C76.1 U3.30(OA_2-)
PERN6_C: C140.1 U3.16(IA_2-)
PERN7: C78.1 U3.28(OA_3-)
PERN7_C: C142.1 U3.18(IA_3-)
PERN8: C80.1 U4.44(OB_0-)
PERN8_C: C144.1 U4.2(IB_0-)
PERN9: C82.1 U4.42(OB_1-)
PERN9_C: C146.1 U4.4(IB_1-)
PERN10: C84.1 U4.39(OB_2-)
PERN10_C: C148.1 U4.6(IB_2-)
PERN11: C86.1 U4.37(OB_3-)
PERN11_C: C150.1 U4.8(IB_3-)
PERN12: C88.1 U4.34(OA_0-)
PERN12_C: C152.1 U4.11(IA_0-)
PERN13: C90.1 U4.32(OA_1-)
PERN13_C: C154.1 U4.13(IA_1-)
PERN14: C92.1 U4.30(OA_2-)
PERN14_C: C156.1 U4.16(IA_2-)
PERN15: C94.1 U4.28(OA_3-)
PERN15_C: C158.1 U4.18(IA_3-)
PERP0: C63.1 U3.45(OB_0+)
PERP0_C: C127.1 U3.1(IB_0+)
PERP1: C65.1 U3.43(OB_1+)
PERP1_C: C129.1 U3.3(IB_1+)
PERP2: C67.1 U3.40(OB_2+)
PERP2_C: C131.1 U3.5(IB_2+)
PERP3: C69.1 U3.38(OB_3+)
PERP3_C: C133.1 U3.7(IB_3+)
PERP4: C71.1 U3.35(OA_0+)
PERP4_C: C135.1 U3.10(IA_0+)
PERP5: C73.1 U3.33(OA_1+)
PERP5_C: C137.1 U3.12(IA_1+)
PERP6: C75.1 U3.31(OA_2+)
PERP6_C: C139.1 U3.15(IA_2+)
PERP7: C77.1 U3.29(OA_3+)
PERP7_C: C141.1 U3.17(IA_3+)
PERP8: C79.1 U4.45(OB_0+)
PERP8_C: C143.1 U4.1(IB_0+)
PERP9: C81.1 U4.43(OB_1+)
PERP9_C: C145.1 U4.3(IB_1+)
PERP10: C83.1 U4.40(OB_2+)
PERP10_C: C147.1 U4.5(IB_2+)
PERP11: C85.1 U4.38(OB_3+)
PERP11_C: C149.1 U4.7(IB_3+)
PERP12: C87.1 U4.35(OA_0+)
PERP12_C: C151.1 U4.10(IA_0+)
PERP13: C89.1 U4.33(OA_1+)
PERP13_C: C153.1 U4.12(IA_1+)
PERP14: C91.1 U4.31(OA_2+)
PERP14_C: C155.1 U4.15(IA_2+)
PERP15: C93.1 U4.29(OA_3+)
PERP15_C: C157.1 U4.17(IA_3+)
PERST: J1.A11 J2.A11
PETN0: C32.2 U1.2(IB_0-)
PETN0_C: C96.2 U1.44(OB_0-)
PETN1: C34.2 U1.4(IB_1-)
PETN1_C: C98.2 U1.42(OB_1-)
PETN2: C36.2 U1.6(IB_2-)
PETN2_C: C100.2 U1.39(OB_2-)
PETN3: C38.2 U1.8(IB_3-)
PETN3_C: C102.2 U1.37(OB_3-)
PETN4: C40.2 U1.11(IA_0-)
PETN4_C: C104.2 U1.34(OA_0-)
PETN5: C42.2 U1.13(IA_1-)
PETN5_C: C106.2 U1.32(OA_1-)
PETN6: C44.2 U1.16(IA_2-)
PETN6_C: C108.2 U1.30(OA_2-)
PETN7: C46.2 U1.18(IA_3-)
PETN7_C: C110.2 U1.28(OA_3-)
PETN8: C48.2 U2.2(IB_0-)
PETN8_C: C112.2 U2.44(OB_0-)
PETN9: C50.2 U2.4(IB_1-)
PETN9_C: C114.2 U2.42(OB_1-)
PETN10: C52.2 U2.6(IB_2-)
PETN10_C: C116.2 U2.39(OB_2-)
PETN11: C54.2 U2.8(IB_3-)
PETN11_C: C118.2 U2.37(OB_3-)
PETN12: C56.2 U2.11(IA_0-)
PETN12_C: C120.2 U2.34(OA_0-)
PETN13: C58.2 U2.13(IA_1-)
PETN13_C: C122.2 U2.32(OA_1-)
PETN14: C60.2 U2.16(IA_2-)
PETN14_C: C124.2 U2.30(OA_2-)
PETN15: C62.2 U2.18(IA_3-)
PETN15_C: C126.2 U2.28(OA_3-)
PETP0: C31.2 U1.1(IB_0+)
PETP0_C: C95.2 U1.45(OB_0+)
PETP1: C33.2 U1.3(IB_1+)
PETP1_C: C97.2 U1.43(OB_1+)
PETP2: C35.2 U1.5(IB_2+)
PETP2_C: C99.2 U1.40(OB_2+)
PETP3: C37.2 U1.7(IB_3+)
PETP3_C: C101.2 U1.38(OB_3+)
PETP4: C39.2 U1.10(IA_0+)
PETP4_C: C103.2 U1.35(OA_0+)
PETP5: C41.2 U1.12(IA_1+)
PETP5_C: C105.2 U1.33(OA_1+)
PETP6: C43.2 U1.15(IA_2+)
PETP6_C: C107.2 U1.31(OA_2+)
PETP7: C45.2 U1.17(IA_3+)
PETP7_C: C109.2 U1.29(OA_3+)
PETP8: C47.2 U2.1(IB_0+)
PETP8_C: C111.2 U2.45(OB_0+)
PETP9: C49.2 U2.3(IB_1+)
PETP9_C: C113.2 U2.43(OB_1+)
PETP10: C51.2 U2.5(IB_2+)
PETP10_C: C115.2 U2.40(OB_2+)
PETP11: C53.2 U2.7(IB_3+)
PETP11_C: C117.2 U2.38(OB_3+)
PETP12: C55.2 U2.10(IA_0+)
PETP12_C: C119.2 U2.35(OA_0+)
PETP13: C57.2 U2.12(IA_1+)
PETP13_C: C121.2 U2.33(OA_1+)
PETP14: C59.2 U2.15(IA_2+)
PETP14_C: C123.2 U2.31(OA_2+)
PETP15: C61.2 U2.17(IA_3+)
PETP15_C: C125.2 U2.29(OA_3+)
PRSNT: SW9.4(A4) SW14.5(B4) SW14.6(B3) SW14.7(B2) SW14.8(B1) U1.52(/PRSNT) U2.52(/PRSNT) U3.52(/PRSNT) U4.52(/PRSNT)
PRSNT1: J1.A1 J2.A1
PRSNT2_1: J1.B17 J2.B17 SW14.1(A1)
PRSNT2_2: J1.B31 J2.B31 SW14.2(A2)
PRSNT2_3: J1.B48 J2.B48 SW14.3(A3)
PRSNT2_4: J1.B81 J2.B81 SW14.4(A4)
RATE: SW10.7(B6) SW10.8(B5) SW10.9(B4) U1.21(RATE) U2.21(RATE) U3.21(RATE) U4.21(RATE)
RD_EN2: SW8.7(B2) SW9.1(A1) U2.26(SD_TH/RD_EN)
RD_EN3: SW8.6(B3) SW9.2(A2) U3.26(SD_TH/RD_EN)
RD_EN4: SW8.5(B4) SW9.3(A3) U4.26(SD_TH/RD_EN)
REFCLKN: J1.A14 J2.A14
REFCLKP: J1.A13 J2.A13
RES: SW6.7(B6) SW6.8(B5) SW6.9(B4) U1.23(RES) U2.23(RES) U3.23(RES) U4.23(RES)
RSV2: J1.B30 J2.B30
RSVD: J1.A19 J2.A19
RSVD1: J1.B12 J2.B12
RSVD2: J1.B82 J2.B82
RSVD3: J1.A32 J2.A32
RSVD4: J1.A33 J2.A33
RSVD5: J1.A50 J2.A50
RXDET: SW10.10(B3) SW10.11(B2) SW10.12(B1) U1.22(RXDET) U2.22(RXDET) U3.22(RXDET) U4.22(RXDET)
SCL: J8.3 J9.6 R55.1 SW4.3(B2) SW12.4(B1)
SD_TH: SW6.10(B3) SW6.11(B2) SW6.12(B1) SW8.1(A1) SW8.2(A2) SW8.3(A3) SW8.4(A4) U1.26(SD_TH/RD_EN)
SDA: J8.4 J9.5 R56.1 SW4.4(B1) SW12.3(B2)
SMCLK: J1.B5 J2.B5 SW12.1(A1)
SMDAT: J1.B6 J2.B6 SW12.2(A2)
VIH: J7.2 J9.8 R11.1 R14.1 R17.1 R20.1 R23.1 R26.1 R29.1 R32.1 R35.1 R38.1 R41.1 R44.1 R47.1 R53.1 R54.2 R55.2 R56.2
VOUT1_2: C27.1 C29.1 J4.2 J4.3 J7.3 R1.2 U5.5(OUTPUT)
VOUT3_4: C28.1 C30.1 J6.2 J6.3 R4.2 U6.5(OUTPUT)
WAKE: J1.B11 J2.B11
N14347575: C29.2 R1.1 R2.2 U5.6(ADJ)
N14347651: C25.1 U5.1(BYPASS)
N14347847: R3.2 U5.8(S_DWN)
N14379250: C26.1 U6.1(BYPASS)
N14379574: C30.2 R4.1 R5.2 U6.6(ADJ)
N14379914: R6.2 U6.8(S_DWN)
N14519010: R53.2 SW8.8(B1) SW13.1
N14524358: J9.3 R52.2
N14524360: J9.2 R51.2
N14524362: J9.1 R50.2
N14693554: J9.7 R54.1
N143603151: R14.2 SW1.4(A4)
N143603431: R15.2 SW1.5(A5)
N143603671: R13.2 SW1.3(A3)
N143605131: R12.2 SW1.2(A2)
N143605431: R16.2 SW1.6(A6)
N143605671: R11.2 SW1.1(A1)
N144765660: C109.1 J2.B45
N144766261: C142.2 J2.A48
N144766561: C153.2 J2.A72
N144766980: C99.1 J2.B23
N144767221: C158.2 J2.A81
N144767760: C123.1 J2.B74
N144768181: C132.2 J2.A26
N144768421: C130.2 J2.A22
N144768781: C147.2 J2.A60
N144769021: C143.2 J2.A52
N144769680: C95.1 J2.B14
N144769921: C154.2 J2.A73
N144770280: C106.1 J2.B38
N144770640: C115.1 J2.B58
N144770880: C116.1 J2.B59
N144771181: C137.2 J2.A39
N144771420: C108.1 J2.B42
N144771900: C102.1 J2.B28
N144772140: C125.1 J2.B78
N144772500: C120.1 J2.B67
N144772741: C149.2 J2.A64
N144773341: C141.2 J2.A47
N144773581: C133.2 J2.A29
N144774000: C124.1 J2.B75
N144774240: C117.1 J2.B62
N144774480: C98.1 J2.B20
N144775140: C110.1 J2.B46
N144775501: C156.2 J2.A77
N144776160: C114.1 J2.B55
N144776640: C100.1 J2.B24
N144776880: C97.1 J2.B19
N144777181: C151.2 J2.A68
N144777421: C150.2 J2.A65
N144777781: C144.2 J2.A53
N144778201: C146.2 J2.A57
N144778500: C122.1 J2.B71
N144778741: C148.2 J2.A61
N144778981: C140.2 J2.A44
N144779220: C103.1 J2.B33
N144779460: C101.1 J2.B27
N144780060: C121.1 J2.B70
N144780361: C139.2 J2.A43
N144780601: C138.2 J2.A40
N144788221: C157.2 J2.A80
N144788821: C145.2 J2.A56
N144789240: C111.1 J2.B50
N144789780: C107.1 J2.B41
N144790260: C118.1 J2.B63
N144790620: C104.1 J2.B34
N144791101: C129.2 J2.A21
N144791880: C126.1 J2.B79
N144792241: C127.2 J2.A16
N144792841: C135.2 J2.A35
N144793080: C119.1 J2.B66
N144793501: C128.2 J2.A17
N144794040: C113.1 J2.B54
N144794401: C131.2 J2.A25
N144794701: C134.2 J2.A30
N144795060: C96.1 J2.B15
N144795421: C155.2 J2.A76
N144795720: C112.1 J2.B51
N144796260: C105.1 J2.B37
N144796741: C152.2 J2.A69
N144796981: C136.2 J2.A36
N144870501: R19.2 SW2.3(A3)
N144870781: R17.2 SW2.1(A1)
N144871281: R18.2 SW2.2(A2)
N144872111: R25.2 SW3.6(A6)
N144872810: R20.2 SW3.1(A1)
N144872811: R21.2 SW3.2(A2)
N144872812: R22.2 SW3.3(A3)
N144872813: R23.2 SW3.4(A4)
N144872814: R24.2 SW3.5(A5)
N144873671: R29.2 SW5.4(A4)
N144874091: R31.2 SW5.6(A6)
N144874331: R30.2 SW5.5(A5)
N144874811: R28.2 SW5.3(A3)
N144875811: R26.2 SW5.1(A1)
N144876491: R27.2 SW5.2(A2)
N144883340: R38.2 SW10.1(A1)
N144883341: R39.2 SW10.2(A2)
N144883342: R40.2 SW10.3(A3)
N144883343: R41.2 SW10.4(A4)
N144883344: R42.2 SW10.5(A5)
N144883345: R43.2 SW10.6(A6)
N144883781: R44.2 SW11.1(A1)
N144885701: R35.2 SW6.4(A4)
N144886021: R45.2 SW11.2(A2)
N144886681: R37.2 SW6.6(A6)
N144886921: R36.2 SW6.5(A5)
N144888121: R34.2 SW6.3(A3)
N144888661: R49.2 SW11.6(A6)
N144889101: R46.2 SW11.3(A3)
N144890181: R47.2 SW11.4(A4)
N144890984: R48.2 SW11.5(A5)
N144891221: R32.2 SW6.1(A1)
N144891941: R33.2 SW6.2(A2)
N144905650: D1.2(ANODE) R7.1
N144909880: D3.2(ANODE) R9.1
N144912360: D2.2(ANODE) R8.1
N144914850: D4.2(ANODE) R10.1
N708449615: C63.2 J1.A16
N708449616: C64.2 J1.A17
N708449620: C65.2 J1.A21
N708449621: C66.2 J1.A22
N708449624: C67.2 J1.A25
N708449625: C68.2 J1.A26
N708449628: C69.2 J1.A29
N708449629: C70.2 J1.A30
N708449634: C71.2 J1.A35
N708449635: C72.2 J1.A36
N708449638: C73.2 J1.A39
N708449639: C74.2 J1.A40
N708449642: C75.2 J1.A43
N708449643: C76.2 J1.A44
N708449646: C77.2 J1.A47
N708449647: C78.2 J1.A48
N708449651: C79.2 J1.A52
N708449652: C80.2 J1.A53
N708449655: C81.2 J1.A56
N708449656: C82.2 J1.A57
N708449659: C83.2 J1.A60
N708449660: C84.2 J1.A61
N708449663: C85.2 J1.A64
N708449664: C86.2 J1.A65
N708449667: C87.2 J1.A68
N708449668: C88.2 J1.A69
N708449671: C89.2 J1.A72
N708449672: C90.2 J1.A73
N708449675: C91.2 J1.A76
N708449676: C92.2 J1.A77
N708449679: C93.2 J1.A80
N708449680: C94.2 J1.A81
N708449695: C31.1 J1.B14
N708449696: C32.1 J1.B15
N7084496100: C33.1 J1.B19
N7084496101: C34.1 J1.B20
N7084496104: C35.1 J1.B23
N7084496105: C36.1 J1.B24
N7084496108: C37.1 J1.B27
N7084496109: C38.1 J1.B28
N7084496114: C39.1 J1.B33
N7084496115: C40.1 J1.B34
N7084496118: C41.1 J1.B37
N7084496119: C42.1 J1.B38
N7084496122: C43.1 J1.B41
N7084496123: C44.1 J1.B42
N7084496126: C45.1 J1.B45
N7084496127: C46.1 J1.B46
N7084496131: C47.1 J1.B50
N7084496132: C48.1 J1.B51
N7084496135: C49.1 J1.B54
N7084496136: C50.1 J1.B55
N7084496139: C51.1 J1.B58
N7084496140: C52.1 J1.B59
N7084496143: C53.1 J1.B62
N7084496144: C54.1 J1.B63
N7084496147: C55.1 J1.B66
N7084496148: C56.1 J1.B67
N7084496151: C57.1 J1.B70
N7084496152: C58.1 J1.B71
N7084496155: C59.1 J1.B74
N7084496156: C60.1 J1.B75
N7084496159: C61.1 J1.B78
N7084496160: C62.1 J1.B79

Pads without a net: J8 2; U5 2 7; U6 2 7

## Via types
v1: diameter 0.508, hole 0.254, TOP to BOTTOM, 409 vias

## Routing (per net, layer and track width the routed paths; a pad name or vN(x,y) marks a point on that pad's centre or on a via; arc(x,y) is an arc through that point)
12V: length 30.8
  TOP w0.635: J2.A2 v1(46.65,58.21) ; v1(46.65,58.21) v1(47.65,58.21) J2.A3 ; v1(46.65,58.21) 46.14,58.21 v1(45.65,57.72) J2.B1 ; J1.A2 v1(46.65,6.12) ; v1(46.65,6.12) 46.66,6.11 v1(47.65,6.11) J1.A3 ; v1(46.65,6.12) 46.06,6.12 45.65,5.7 J1.B1
  BOTTOM w0.635: v1(46.65,58.21) 46.14,58.21 v1(45.65,57.72) ; v1(46.65,58.21) J2.A2 ; v1(46.65,58.21) v1(47.65,58.21) J2.A3 ; J1.A2 v1(46.65,6.12) 47.64,6.12 v1(47.65,6.11) J1.A3
GND: length 429.1
  TOP w0.508: C160.1 v1(94.93,26.06) ; C28.2 v1(95.31,35.69) ; D1.1 v1(131.12,36.2) ; 84.39,21.87 v1(82.92,21.87) ; U6.3 82.65,40.79 v1(82.51,40.93) ; D3.1 v1(134.05,45.11) ; D2.1 v1(132.86,36.2) ; D4.1 v1(136.97,45.21)
  TOP w0.635: J2.B61 107.65,58.35 v1(108.12,57.88) ; J2.B21 67.65,58.59 v1(67.15,58.09) ; J2.B73 119.65,58.49 v1(120.16,57.98) ; v1(87.14,58.01) 86.65,58.5 J2.B40 ; J2.B44 90.65,58.31 v1(91.1,57.86) ; v1(89.22,57.88) 89.65,58.31 J2.B43 ; J1.B57 103.65,6 v1(104.05,6.4) ; J2.B60 106.65,58.45 v1(106.14,57.93) ; J2.A49 v1(95.65,58.18) ; J1.B16 62.65,5.94 v1(62.09,6.5) ; J1.B7 v1(51.65,6.79) ; v1(71.11,58.01) 71.65,58.55 J2.B25 ; v1(126.1,6.47) 126.65,5.92 J1.B80 ; v1(118.15,58.09) 118.65,58.59 J2.B72 ; J2.B68 114.65,58.45 v1(114.24,58.04) ; J2.B29 75.65,58.56 v1(75.15,58.06) ; R5.1 v1(92.43,43.09) ; SW7.2 v1(91.02,35.2) ; J1.B40 86.65,6.09 v1(87.11,6.55) ; v1(122.16,57.98) 122.65,58.47 J2.B76 ; J2.B35 81.65,58.57 v1(81.17,58.09) ; v1(59.65,6.9) 59.65,6.9 J1.B13 ; v1(95.14,6.58) 95.65,6.06 J1.A49 ; J2.B69 115.65,58.43 v1(116.09,57.98) ; J2.B56 102.65,58.41 v1(102.1,57.86) ; J2.B32 78.65,57.93 v1(78.45,57.73) ; J2.B13 59.65,58.13 v1(59.17,57.65) ; v1(85.08,6.55) 85.65,5.98 J1.B39 ; J2.B57 103.65,58.39 v1(104.15,57.88) ; J1.B60 106.65,5.88 v1(106.06,6.47) ; C27.2 v1(94.41,20.94) ; v1(93.11,57.86) 93.65,58.4 J2.B47 ; J1.B65 111.65,5.87 v1(112.1,6.32) ; v1(126.2,57.96) 126.65,58.41 J2.B80 ; J2.B65 111.65,58.47 v1(112.16,57.96) ; J2.B22 68.65,58.46 v1(69.08,58.04) ; v1(71.11,6.58) 71.65,6.03 J1.B25 ; J1.A4 v1(48.65,6.05) ; J1.B43 89.65,5.94 v1(89.09,6.5) ; v1(73.04,6.63) 72.65,6.24 J1.B26 ; J2.B64 110.65,58.49 v1(110.12,57.96) ; v1(93.1,6.42) 93.65,5.88 J1.B47 ; v1(120.08,6.35) 119.65,5.92 J1.B73 ; J2.A4 v1(48.65,58.18) ; J1.B52 98.65,5.98 v1(98.08,6.55) ; J1.B44 90.65,5.98 v1(91.07,6.4) ; J1.B69 115.65,5.88 v1(116.07,6.3) ; R2.1 v1(92.71,23.53) ; v1(110.12,6.32) 110.65,5.79 J1.B64 ; J1.B35 81.65,6.35 v1(81.14,6.85) ; v1(98.13,57.88) 98.65,58.4 J2.B52 ; J2.B36 82.65,58.46 v1(83.12,57.98) ; v1(118.07,6.37) 118.65,5.79 J1.B72 ; J2.A18 v1(64.65,58.18) ; J1.B68 114.65,5.76 v1(114.08,6.32) ; v1(100.14,58.04) 99.65,58.53 J2.B53 ; v1(64.12,6.55) 64.65,6.02 J1.A18 ; J1.B22 68.65,6.12 v1(69.1,6.58) ; J2.B39 85.65,58.48 v1(85.21,58.04) ; J2.B16 62.65,58.47 v1(62.24,58.06) ; v1(100.06,6.55) 99.65,6.14 J1.B53 ; v1(78.37,6.55) 78.37,6.55 78.65,6.27 J1.B32 ; v1(83.11,6.66) 82.65,6.21 J1.B36 ; v1(122.11,6.42) 122.65,5.88 J1.B76 ; v1(124.09,6.42) 123.65,5.98 J1.B77 ; J2.B7 51.65,58.31 v1(51,57.66) ; J1.B56 102.65,5.89 v1(102.1,6.45) ; v1(73.17,57.96) 72.65,58.48 J2.B26 ; v1(124.14,57.98) 123.65,58.48 J2.B77 ; J1.B61 107.65,5.88 v1(108.14,6.37) ; J1.B29 75.65,6.15 v1(75.1,6.7) ; SW7.1 v1(91.05,32.66) ; v1(67.12,6.52) 67.65,5.99 J1.B21
  BOTTOM w0.508: J2.A18 v1(64.65,58.18) ; J2.A49 v1(95.65,58.18) ; v1(69.08,58.04) 69.65,58.61 J2.A23 ; v1(75.15,58.06) 74.65,58.56 J2.A28 ; J2.A31 77.65,58.53 v1(78.45,57.73) ; J2.A51 97.65,58.37 v1(98.13,57.88) ; v1(110.12,57.96) 109.65,58.43 J2.A63 ; v1(116.09,57.98) 116.65,58.54 J2.A70 ; v1(89.22,57.88) 88.65,58.45 J2.A42 ; v1(81.17,58.09) 80.65,58.6 J2.A34 ; J2.A62 108.65,58.42 v1(108.12,57.88) ; v1(71.11,58.01) 70.65,58.47 J2.A24 ; v1(106.14,57.93) 105.65,58.42 J2.A59 ; J1.A82 128.65,6.87 v1(128,7.52) ; v1(126.2,57.96) 125.65,58.51 J2.A79 ; J2.A55 101.65,58.31 v1(102.1,57.86) ; v1(73.17,57.96) 73.65,58.44 J2.A27 ; J2.A82 128.65,58.58 v1(129.3,57.92) ; v1(85.21,58.04) 84.65,58.59 J2.A38 ; v1(100.14,58.04) 100.65,58.54 J2.A54 ; J2.A78 124.65,58.49 v1(124.14,57.98) ; C23.1 83.06,22.01 v1(82.92,21.87) ; v1(62.24,58.06) 61.65,58.66 J2.A15 ; v1(67.15,58.09) 66.65,58.58 J2.A20 ; v1(120.16,57.98) 120.65,58.48 J2.A74 ; v1(87.14,58.01) 87.65,58.52 J2.A41 ; C21.1 v1(100.77,27.58) ; v1(118.15,58.09) 117.65,58.59 J2.A71 ; v1(114.24,58.04) 113.65,58.62 J2.A67 ; v1(112.16,57.96) 112.65,58.45 J2.A66 ; v1(93.11,57.86) 92.65,58.31 J2.A46 ; J2.A37 83.65,58.51 v1(83.12,57.98) ; v1(59.17,57.65) 58.65,58.18 J2.A12 ; v1(91.1,57.86) 91.65,58.41 J2.A45 ; J2.A4 v1(48.65,58.18) ; v1(122.16,57.98) 121.65,58.5 J2.A75 ; v1(104.15,57.88) 104.65,58.38 J2.A58
  BOTTOM w0.635: J1.A31 77.65,5.83 v1(78.37,6.55) ; R40.1 v1(156.32,42.01) ; v1(59.65,6.9) 58.65,5.91 J1.A12 ; C24.1 v1(82.51,40.93) ; R48.1 v1(156.58,28.93) ; v1(118.07,6.37) 117.65,5.95 J1.A71 ; J1.A38 84.65,6.12 v1(85.08,6.55) ; R18.1 v1(22.92,48.84) ; J1.A15 61.65,6.06 v1(62.09,6.5) ; v1(100.06,6.55) 100.65,5.96 J1.A54 ; v1(67.12,6.52) 66.65,6.05 J1.A20 ; J1.A78 124.65,5.87 v1(124.09,6.42) ; v1(89.09,6.5) 88.65,6.06 J1.A42 ; R21.1 v1(20.13,35.66) ; J1.A66 112.65,5.77 v1(112.1,6.32) ; J1.A46 92.65,5.97 v1(93.1,6.42) ; J1.A41 87.65,6.01 v1(87.11,6.55) ; R30.1 v1(28,23.21) ; J1.A59 105.65,6.07 v1(106.06,6.47) ; v1(91.07,6.4) 91.65,5.82 J1.A45 ; J1.A75 121.65,5.96 v1(122.11,6.42) ; R49.1 v1(156.45,31.47) ; v1(110.12,6.32) 109.65,5.85 J1.A63 ; v1(75.1,6.7) 74.65,6.26 J1.A28 ; v1(73.04,6.63) 73.65,6.01 J1.A27 ; J1.A79 125.65,6.02 v1(126.1,6.47) ; v1(120.08,6.35) 120.65,5.78 J1.A74 ; R43.1 v1(156.32,49.63) ; R42.1 v1(156.32,47.09) ; R28.1 v1(22.92,23.21) ; R13.1 v1(26.48,58.87) ; R50.1 v1(132.28,17.85) ; J1.A62 108.65,5.86 v1(108.14,6.37) ; R27.1 v1(20.38,23.21) ; C161.1 v1(99.63,37.61) ; v1(104.05,6.4) 104.65,5.8 J1.A58 ; v1(116.07,6.3) 116.21,6.15 116.25,6.15 116.55,5.85 116.55,5.81 116.65,5.71 J1.A70 ; v1(81.14,6.85) 80.65,6.36 J1.A34 ; R37.1 v1(144.01,61.95) ; C25.2 v1(85.68,25.23) ; J1.A67 113.65,5.89 v1(114.08,6.32) ; v1(102.1,6.45) 101.65,6 J1.A55 ; C26.2 v1(85.3,44.28) ; R12.1 v1(29.02,58.87) ; J1.A37 83.65,6.12 v1(83.11,6.66) ; v1(64.12,6.55) 64.65,6.02 J1.A18 ; R51.1 v1(142.18,20.44) ; R39.1 v1(156.45,39.47) ; R36.1 v1(144.13,59.41) ; R15.1 v1(21.53,58.87) ; C22.1 v1(100.08,42.66) ; v1(95.14,6.58) 95.65,6.06 J1.A49 ; R25.1 v1(30.29,35.66) ; R16.1 v1(18.86,58.87) ; v1(69.1,6.58) 69.65,6.03 J1.A23 ; v1(71.11,6.58) 70.65,6.12 J1.A24 ; J1.A4 v1(48.65,6.05) ; v1(98.08,6.55) 97.65,6.12 J1.A51 ; R34.1 v1(144.13,54.33) ; R24.1 v1(27.75,35.66) ; R46.1 v1(156.58,23.85) ; R45.1 v1(156.71,21.31) ; R33.1 v1(144.13,51.79) ; R52.1 v1(142.05,22.98) ; R19.1 v1(20.26,48.84) ; R31.1 v1(30.54,23.21) ; R22.1 v1(22.67,35.66)
  vias: v1(65.65,39.75) v1(65.65,24.51) v1(66.87,41.12) v1(66.87,39.8) v1(66.87,25.88) v1(66.87,24.56) v1(66.89,38.45) v1(66.89,23.21) v1(68.36,41.14) v1(68.36,39.77) v1(68.36,38.45) v1(68.36,25.9) v1(68.36,24.53) v1(68.36,23.21) v1(69.86,39.8) v1(69.86,38.45) v1(69.86,24.56) v1(69.86,23.21) v1(69.89,41.14) v1(69.89,25.9) v1(71.36,41.17) v1(71.36,39.8) v1(71.36,38.43) v1(71.36,25.93) v1(71.36,24.56) v1(71.36,23.19) v1(72.38,39.8) v1(72.38,24.56) v1(85.89,39.82) v1(86.37,21.05) v1(86.68,39.82) v1(87.19,21.03) v1(87.49,39.82) v1(88.07,21.03) v1(110.45,39.75) v1(110.45,24.51) v1(111.67,41.12) v1(111.67,39.8) v1(111.67,25.88) v1(111.67,24.56) v1(111.7,38.45) v1(111.7,23.21) v1(113.17,41.14) v1(113.17,39.77) v1(113.17,38.45) v1(113.17,25.9) v1(113.17,24.53) v1(113.17,23.21) v1(114.67,39.8) v1(114.67,38.45) v1(114.67,24.56) v1(114.67,23.21) v1(114.69,41.14) v1(114.69,25.9) v1(116.17,41.17) v1(116.17,39.8) v1(116.17,38.43) v1(116.17,25.93) v1(116.17,24.56) v1(116.17,23.19) v1(117.18,39.8) v1(117.18,24.56)
VDD1: length 8.4
  TOP w0.229: U1.51 63.39,24.03 63.39,24.03 v1(63.26,24.03)
  TOP w0.254: U1.9 68.77,21.09 v1(68.77,21.09) ; U1.14 v1(71.27,21.08) ; U1.41 v1(66.77,27.98) ; U1.36 v1(69.27,27.97)
  BOTTOM w0.292: v1(66.77,27.98) 66.74,27.95 C4.2 ; v1(63.26,24.03) 63.36,24.03 63.37,24.03 64.35,24.03 64.36,24.03 C2.2 ; C1.2 v1(68.77,21.09) ; v1(69.27,27.97) 69.27,27.17 69.28,27.17 C3.2 ; C5.2 71.31,21.11 v1(71.27,21.08)
VDD2: length 8
  TOP w0.229: v1(114.08,27.96) 114.08,27.96 U2.36 ; U2.51 108.14,24.03 v1(108.14,24.04)
  TOP w0.254: U2.41 111.58,27.97 v1(111.6,27.99) ; v1(116.09,21.1) 116.09,21.13 116.08,21.14 U2.14 ; U2.9 v1(113.58,21.1)
  BOTTOM w0.292: C7.2 111.54,27.93 v1(111.6,27.99) ; C8.2 108.15,24.03 v1(108.14,24.04) ; v1(113.58,21.1) 113.58,21.1 C9.2 ; v1(116.09,21.1) 116.12,21.13 C10.2 ; C6.2 v1(114.08,27.96)
VDD3: length 7.9
  TOP w0.292: v1(63.35,40.27) 63.35,40.28 C13.2 ; C15.2 66.74,36.38 v1(66.77,36.34) ; v1(71.27,43.2) 71.31,43.17 C11.2 ; C14.2 69.28,36.35 v1(69.27,36.34) ; C12.2 68.77,43.2 v1(68.77,43.2)
  BOTTOM w0.229: U3.51 v1(63.35,40.27)
  BOTTOM w0.254: U3.14 v1(71.27,43.2) ; U3.41 v1(66.77,36.34) ; U3.9 v1(68.77,43.2) ; U3.36 v1(69.27,36.34)
VDD4: length 7.9
  TOP w0.292: C20.2 111.54,36.38 v1(111.58,36.34) ; v1(108.14,40.28) 108.14,40.28 C18.2 ; C17.2 113.58,43.2 v1(113.58,43.2) ; C16.2 116.12,43.19 v1(116.1,43.21) ; C19.2 114.08,36.35 v1(114.08,36.34)
  BOTTOM w0.229: U4.51 108.15,40.27 108.14,40.28 v1(108.14,40.28)
  BOTTOM w0.254: U4.9 v1(113.58,43.2) ; U4.36 v1(114.08,36.34) ; U4.41 v1(111.58,36.34)
  BOTTOM w0.292: v1(116.1,43.21) 116.08,43.19 U4.14
VDD_SEL1_2: length 78.9
  TOP w0.229: 75.8,25.83 75.5,25.53 U1.25 ; U2.25 v1(120.33,25.53)
  TOP w0.292: 75.8,25.83 75.83,25.86 76.77,25.86 77.43,26.52
  TOP w0.508: 77.43,26.52 78.59,27.68
  TOP w0.635: 78.59,27.68 80.15,29.24
  TOP w0.762: 80.15,29.24 82.44,31.53 v1(82.44,32.66) SW7.4
  POWER1 w0.762: v1(82.44,32.66) 82.08,32.31 82.08,19.78 86.86,15.01 106.62,15.01 108.98,17.37 108.98,19.86 v1(108.5,20.34)
  BOTTOM w0.508: v1(120.33,25.53) 120.33,25.65 119.88,26.11 119.22,26.11
  BOTTOM w0.762: 119.22,26.11 118.44,26.11 117.95,25.61 117.95,21.55 117.74,21.34 117.74,21.34 116.21,19.81 109.03,19.81 v1(108.5,20.34)
